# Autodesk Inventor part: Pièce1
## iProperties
Shininess: 20.0
Angle Display Precision: 2
Document Length Units: 11269
Document Angle Units: 11279
Document Time Units: 11290
Document Mass Units: 11283
Document Length Units Precision: 3
Document Angle Units Precision: 2
Compacted: True
Created: 2009-07
Part Number: Pièce1
Material: Par défaut
Document SubType Name: Modélisation
Designer: EL
Density: 1 g/cm^3
Density: 0.0
Volumn: 0.0
Area: 0.0
PropertySet Name: Model Information
Control State: 0
Master: False
Checked Out: False
Author: EL
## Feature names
1. Extrusion1
2. Extrusion2
3. Extrusion3
4. Extrusion4
5. Extrusion5
6. Extrusion6
